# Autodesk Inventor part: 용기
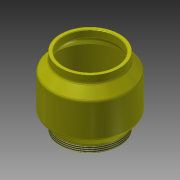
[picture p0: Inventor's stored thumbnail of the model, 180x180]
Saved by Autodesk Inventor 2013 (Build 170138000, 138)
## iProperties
Created: 2018-01
Part Number: 용기
Material: ABS 플라스틱
Document SubType Name: Modeling
Designer: mduedu
Density: 1 g/cm^3
Author: mduedu
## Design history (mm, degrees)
sketch "스케치1"
  geometry: L1 (0, 0)-(-35, 0); L2 (-35, 0)-(-35, 9); L3 (-35, 9)-(-45, 20); L4 (-45, 20)-(-45, 60); L5 (-45, 60)-(-35, 71); L6 (-35, 71)-(-35, 80); L7 (-35, 80)-(0, 80); L8 (0, 80)-(0, 0)
  constraints: 16 end point, 3 collinear, 3 parallel, 1 horizontal, 1 perpendicular
  dimensions: "d0" = 9 distance of L1.end L2.end; "d2" = 70 diameter of L2 L8; "d3" = 20 distance from line of L3.end L1; "d4" = 60 distance from line of L4.end L1; "d5" = 20 distance from line of L4.end L7; "d6" = 90 diameter of L4 L8
revolve "회전1" sketch "스케치1" stored, may be unused: angle "d7" = 90 deg
fillet "모깎기1" dims "d8" = 3
feature "쉘1" dims "d9" = 4
chamfer "모따기1" distance "d11" = 0.5; stored, may be unused: second distance "d12" = 2, angle "d13" = 45 deg
feature "스레드1" dims "d14" = 7, "d15" = 0
node "솔리드1"
